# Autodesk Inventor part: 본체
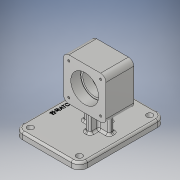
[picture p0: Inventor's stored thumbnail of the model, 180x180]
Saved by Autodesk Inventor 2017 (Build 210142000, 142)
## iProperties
Part Number: 본체
Material: 알루미늄 6061
Document SubType Name: Modeling
Designer: 00-00
Density: 2.7 g/cm^3
Appearance: 알루미늄 - 평지
Mass: 683.576 g
Surface Area: 544.314 cm^2
Volume: 253.176 cm^3
Author: 00-00
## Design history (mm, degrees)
sketch "스케치1"
  geometry: L1 (32, -32)-(-32, -32); L2 (-32, -32)-(-32, 32); L3 (-32, 32)-(32, 32); L4 (32, 32)-(32, -32); L5 (32, -32)-(-32, 32); L6 (-32, -32)-(32, 32); 1 further point
  constraints: 12 end point, 2 midpoint, 2 parallel, 1 horizontal, 1 perpendicular
  dimensions: "d0" = 64 distance of L2.end L3.end; "d1" = 64 distance of L3.end L1.start
extrude "돌출1" new body sketch "스케치1" stored distance "d2" = 42; taper "d3" = 0 deg
node "작업 평면1"
sketch "스케치2"
  geometry: 1 further point
fillet "모깎기1" dims "d5" = 8
sketch "스케치3"
  geometry: L1 (28, 17)-(20, 17); L2 (20, 17)-(20, 25); L3 (20, 25)-(28, 25); L4 (28, 25)-(28, 17); L5 (28, 17)-(20, 25); L6 (20, 17)-(28, 25); 1 further point
  constraints: 12 end point, 2 midpoint, 2 parallel, 1 horizontal, 1 perpendicular
  dimensions: "d6" = 8 distance of L2.end L3.end; "d7" = 8 distance of L3.end L1.start
extrude "돌출2" join sketch "스케치3" distance "d8" = 28; taper "d9" = 0 deg
sketch "스케치4"
  geometry: 1 further point
sketch "스케치5"
  geometry: L1 (36, -65)-(-62, -65); L2 (-62, -65)-(-62, 65); L3 (-62, 65)-(36, 65); L4 (36, 65)-(36, -65); 1 further point
  constraints: 8 end point, 2 parallel, 1 horizontal, 1 perpendicular
  dimensions: "d10" = 98 distance of L1.start L1.end; "d11" = 130 distance of L1.end L2.end; "d15" = 62 distance from line of L2 point (0, 0); "d16" = 65 distance from line of L3 point (0, 0)
extrude "돌출3" join sketch "스케치5" distance "d17" = 10; taper "d18" = 0 deg
sketch "스케치7"
  geometry: L1 (20, -36.719)-(20, -60); L2 (-20, -37)-(-20, -60); L3 (36, -60)-(-62, -60) reference; 1 further point
  constraints: 4 end point, 2 point on line, 2 vertical
  dimensions: "d19" = 20 distance from line of point (0, 0) L2; "d20" = 20 distance from line of point (0, 0) L1
feature "리브1" dims "d21" = 1, "d22" = 8, "d23" = 0, "d24" = 0, "d25" = 1, "d26" = 1
feature "리브2" dims "d27" = 1, "d28" = 8, "d29" = 0, "d30" = 0, "d31" = 1, "d32" = 1
sketch "스케치8"
  geometry: L1 (-37, -17)-(-60, -17); L2 (-35, 17)-(-60, 17); L3 (-60, -65)-(-60, 65) reference; 1 further point
  constraints: 4 end point, 2 horizontal, 2 point on line
  dimensions: "d33" = 17 distance from line of point (0, 0) L2; "d34" = 17 distance from line of point (0, 0) L1
feature "리브3" dims "d35" = 1, "d36" = 8, "d37" = 0, "d38" = 0, "d39" = 1, "d40" = 1
feature "리브4" dims "d41" = 1, "d42" = 8, "d43" = 0, "d44" = 0, "d45" = 1, "d46" = 1
fillet "모깎기2" dims "d47" = 3
fillet "모깎기3" dims "d48" = 3
fillet "모깎기4" dims "d49" = 3
fillet "모깎기5" dims "d50" = 12
fillet "모깎기6" dims "d51" = 3
sketch "스케치9"
  geometry: L1 (17, 7)-(7, 7) reference; L2 (23, -1)-(23, 1) reference; L3 (7, -7)-(17, -7) reference; L4 (7, -14)-(7, -7) reference; L5 (-1, -20)-(1, -20) reference; L6 (-7, -7)-(-7, -14) reference; L7 (-17, -7)-(-7, -7) reference; L8 (-23, 1)-(-23, -1) reference; L9 (-7, 7)-(-17, 7) reference; L10 (-7, 14)-(-7, 7) reference; L11 (1, 20)-(-1, 20) reference; L12 (7, 7)-(7, 14) reference; L13 (33, 53)-(33, -53) reference; L14 (-50, 62)-(24, 62) reference; L15 (-59, -53)-(-59, 53) reference; L16 (24, -62)-(-50, -62) reference; C1 r 4.5 at (-50, -53); C2 r 4.5 at (-50, 53); C3 r 4.5 at (24, 53); C4 r 4.5 at (24, -53); A1 r 6 centre (17, 1) between (23, 1) and (17, 7) reference; A2 r 6 centre (17, -1) between (17, -7) and (23, -1) reference; A3 r 6 centre (1, -14) between (1, -20) and (7, -14) reference; A4 r 6 centre (-1, -14) between (-7, -14) and (-1, -20) reference; A5 r 6 centre (-17, -1) between (-23, -1) and (-17, -7) reference; A6 r 6 centre (-17, 1) between (-17, 7) and (-23, 1) reference; A7 r 6 centre (-1, 14) between (-1, 20) and (-7, 14) reference; A8 r 6 centre (1, 14) between (7, 14) and (1, 20) reference; A9 r 9 centre (24, 53) between (33, 53) and (24, 62) reference; A10 r 9 centre (-50, 53) between (-50, 62) and (-59, 53) reference; A11 r 9 centre (-50, -53) between (-59, -53) and (-50, -62) reference; A12 r 9 centre (24, -53) between (24, -62) and (33, -53) reference; 1 further point
  constraints: 4 centre point, 4 coincident
  dimensions: "d52" = 9 diameter of C1; "d53" = 9 diameter of C2; "d56" = 9 diameter of C3; "d57" = 9 diameter of C4
  node "투영된 루프1"
extrude "돌출4" cut sketch "스케치9" stored distance "d54" = 10; taper "d55" = 0 deg
extrude "돌출5" cut sketch "스케치9" stored distance "d58" = 10; taper "d59" = 0 deg
sketch "스케치10"
  geometry: L1 (0, 40.5)-(0, -40.5); L2 (21, 21)-(21, 6); L3 (24, 21)-(-24, 21) reference; L4 (21, 6)-(18, 6); L5 (18, 6)-(18, -6); L6 (18, -6)-(21, -6); L7 (21, -6)-(21, -21); L8 (21, 21)-(0, 21); L9 (21, -21)-(0, -21); L10 (-24, -21)-(24, -21) reference; L11 (0, 21)-(0, -21); 2 further points
  constraints: 18 end point, 5 perpendicular, 3 midpoint, 2 point on line, 1 coincident, 1 collinear, 1 vertical
  dimensions: "d60" = 42 diameter of L2 L1; "d61" = 42 diameter of L7 L1; "d62" = 36 diameter of L5 L1; "d63" = 15 distance of L2.start L2.end; "d64" = 15 distance of L6.end L7.end
revolve "회전1" sketch "스케치10" stored, may be unused: angle "d65" = 90 deg
fillet "모깎기7" dims "d66" = 0.3
sketch "스케치11"
  geometry: 5 further points
  dimensions: "d67" = 24 horizontal distance of point (0, 0) point (-24, 24); "d68" = 24 horizontal distance of point (0, 0) point (24, 24); "d69" = 24 horizontal distance of point (0, 0) point (-24, 24); "d70" = 24 horizontal distance of point (0, 0) point (-24, -24); "d71" = 24 horizontal distance of point (0, 0) point (24, 24); "d72" = 24 horizontal distance of point (0, 0) point (24, -24); "d73" = 24 horizontal distance of point (24, -24) point (0, 0); "d74" = 24 horizontal distance of point (0, 0) point (-24, -24)
hole "구멍1" sketch "스케치11" at (24, 24), (-24, 24), (-24, -24), (24, -24) diameter "d75" = 3.242; stored, may be unused: countersink angle "d79" = 90 deg, drill point angle "d81" = 118 deg; dims "d76" = 8, "d77" = 4, "d78" = 2, "d80" = 10
sketch "스케치12"
  geometry: 5 further points
  dimensions: "d82" = 24 horizontal distance of point (0, 0) point (24, 24); "d83" = 24 horizontal distance of point (0, 0) point (-24, 24); "d84" = 24 horizontal distance of point (0, 0) point (-24, -24); "d85" = 24 horizontal distance of point (0, 0) point (-24, 24); "d86" = 24 horizontal distance of point (0, 0) point (-24, -24); "d87" = 24 horizontal distance of point (0, 0) point (24, -24); "d88" = 24 horizontal distance of point (24, -24) point (0, 0); "d89" = 24 horizontal distance of point (0, 0) point (24, 24)
hole "구멍2" sketch "스케치12" at (-24, 24), (24, 24), (24, -24), (-24, -24) diameter "d90" = 3.242; stored, may be unused: countersink angle "d94" = 90 deg, drill point angle "d96" = 118 deg; dims "d91" = 8, "d92" = 4, "d93" = 2, "d95" = 10
sketch "스케치13"
  geometry: L1 (-62, 53)-(-62, -53) reference; L2 (24, 65)-(-50, 65) reference; 2 further points
  constraints: 1 other
  dimensions: "d97" = 10 distance from line of L1 point (-52, 0); "d98" = 65 distance from line of L2 point (-52, 0)
feature "엠보싱1" sketch "스케치13" dims "d0" = 64, "d1" = 64, "d99" = 0.5, "d100" = 0
node "솔리드1"
